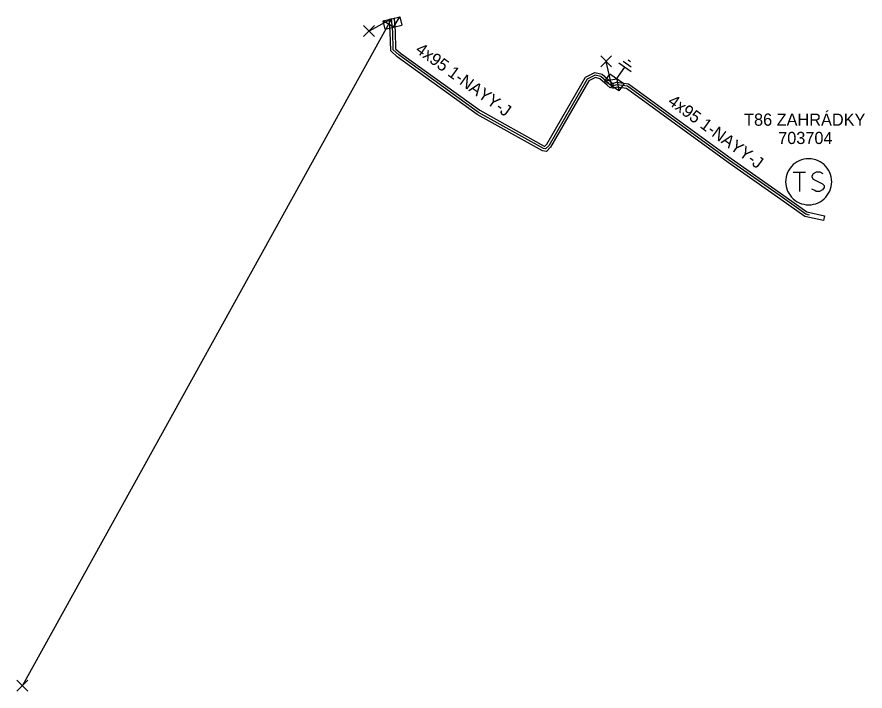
# Model space of a CAD drawing. Extents: x -540247 to -537390, y -1183890 to -1180355.
# Drawn here: x -539006.3 to -538936.7, y -1180876.4 to -1180821.1 of the extents above; entities that cross this region are included whole.
import ezdxf

# ---------------------------------------------------------------- set-up
doc = ezdxf.new("R2010")
doc.units = 0
for name, color, linetype in [('Vrstva 1', 7, 'Continuous'), ('Vrstva 14', 7, 'Continuous'), ('Vrstva 15', 7, 'Continuous'), ('Vrstva 20', 7, 'Continuous'), ('Vrstva 25', 7, 'Continuous'), ('Vrstva 26', 7, 'Continuous'), ('Vrstva 27', 7, 'Continuous'), ('Vrstva 31', 7, 'Continuous'), ('Vrstva 34', 7, 'Continuous'), ('Vrstva 5', 7, 'Continuous'), ('Vrstva 59', 7, 'Continuous'), ('Vrstva 6', 7, 'Continuous'), ('Vrstva 9', 7, 'Continuous')]:
    doc.layers.add(name, color=color, linetype=linetype)

# ---------------------------------------------------------------- blocks, each defined once
blk = doc.blocks.new('NN800')
at = {"layer": 'Vrstva 1'}
for points in [[(-0.442, 0.442), (0.442, -0.442)], [(-0.442, -0.442), (0.442, 0.442)]]:
    blk.add_lwpolyline(points, dxfattribs=at)
blk = doc.blocks.new('NN630')
at = {"layer": 'Vrstva 9'}
for points in [[(-0.003, -0.7), (-0.703, 0)], [(-0.703, -0.7), (-0.703, 0), (0.697, 0), (0.697, -0.7)], [(-0.003, -0.7), (0.697, 0)], [(-0.703, -0.7), (0.697, -0.7)]]:
    blk.add_lwpolyline(points, dxfattribs=at)
blk = doc.blocks.new('NN810')
at = {"layer": 'Vrstva 14'}
for points in [[(0.004, -0.64), (0.004, -1.89)], [(0.629, -1.89), (-0.621, -1.89)], [(0.388, -2.2), (-0.399, -2.2)], [(0.004, -2.515), (-0.124, -2.515)], [(0.137, -2.515), (0.004, -2.515)]]:
    blk.add_lwpolyline(points, dxfattribs=at)
blk = doc.blocks.new('NN610')
at = {"layer": 'Vrstva 6'}
for points in [[(1.883, -0.001), (1.872, 0.196), (1.841, 0.392), (1.79, 0.583), (1.718, 0.768), (1.629, 0.943), (1.521, 1.109), (1.397, 1.263), (1.257, 1.403), (1.103, 1.527), (0.937, 1.635), (0.761, 1.725), (0.577, 1.796), (0.19, 1.878), (0.19, 1.878), (-0.007, 1.889), (-0.205, 1.878), (-0.401, 1.847), (-0.591, 1.796), (-0.777, 1.725), (-0.952, 1.635), (-1.118, 1.527), (-1.272, 1.403), (-1.412, 1.263), (-1.536, 1.109), (-1.644, 0.943), (-1.734, 0.768), (-1.805, 0.583), (-1.856, 0.392), (-1.887, 0.196), (-1.898, -0.001), (-1.887, -0.199), (-1.856, -0.395), (-1.805, -0.585), (-1.734, -0.77), (-1.644, -0.946), (-1.536, -1.112), (-1.411, -1.266), (-1.272, -1.405), (-1.118, -1.53), (-0.952, -1.638), (-0.776, -1.728), (-0.591, -1.799), (-0.401, -1.85), (-0.205, -1.881), (-0.007, -1.892), (0.19, -1.881), (0.385, -1.85), (0.577, -1.799), (0.761, -1.728), (0.937, -1.638), (1.103, -1.53), (1.257, -1.405), (1.397, -1.266), (1.521, -1.112), (1.629, -0.946), (1.718, -0.77), (1.79, -0.585), (1.841, -0.395), (1.872, -0.199), (1.883, -0.001)], [(-1.269, 0.782), (-0.261, 0.782)], [(-0.765, 0.782), (-0.765, -0.792)], [(1.188, 0.656), (0.936, 0.782), (0.621, 0.782), (0.369, 0.656), (0.243, 0.468), (0.243, 0.404), (0.369, 0.216), (1.125, -0.162), (1.251, -0.32), (1.251, -0.478), (1.125, -0.666), (0.873, -0.792), (0.621, -0.792), (0.495, -0.73), (0.243, -0.604)]]:
    blk.add_lwpolyline(points, dxfattribs=at)

msp = doc.modelspace()

# ---------------------------------------------------------------- linework, layer by layer
at = {"layer": 'Vrstva 20'}
for points in [[(-538975.381, -1180821.253), (-538975.29, -1180822.319), (-538975.252, -1180823.72), (-538974.864, -1180824.075), (-538968.353, -1180828.771), (-538963.059, -1180831.71), (-538963.007, -1180831.721), (-538962.851, -1180831.559), (-538959.683, -1180826.058), (-538958.903, -1180825.668), (-538958.315, -1180825.818), (-538957.619, -1180826.419), (-538957.378, -1180826.629), (-538957.642, -1180826.931), (-538957.881, -1180826.721), (-538958.505, -1180826.182), (-538958.857, -1180826.092), (-538959.397, -1180826.362), (-538962.529, -1180831.801), (-538962.873, -1180832.159), (-538963.201, -1180832.089), (-538968.567, -1180829.109), (-538975.116, -1180824.385), (-538975.648, -1180823.9), (-538975.69, -1180822.341), (-538975.779, -1180821.287)], [(-538940.131, -1180837.816), (-538941.682, -1180837.487), (-538943.626, -1180836.093), (-538947.956, -1180833.053), (-538956.298, -1180826.991), (-538957.105, -1180826.873), (-538957.461, -1180826.972), (-538957.558, -1180826.588), (-538957.115, -1180826.467), (-538956.142, -1180826.609), (-538947.724, -1180832.727), (-538943.394, -1180835.767), (-538941.518, -1180837.113), (-538940.049, -1180837.424)]]:
    msp.add_lwpolyline(points, close=True, dxfattribs=at)
at = {"layer": 'Vrstva 5'}
for points in [[(-538957.51, -1180826.78), (-538957.75, -1180826.57), (-538958.41, -1180826), (-538958.88, -1180825.88), (-538959.54, -1180826.21), (-538962.69, -1180831.68), (-538962.94, -1180831.94), (-538963.13, -1180831.9), (-538968.46, -1180828.94), (-538974.99, -1180824.23), (-538975.45, -1180823.81), (-538975.49, -1180822.33), (-538975.58, -1180821.27)], [(-538941.299, -1180837.364), (-538941.6, -1180837.3), (-538943.51, -1180835.93), (-538947.84, -1180832.89), (-538956.22, -1180826.8), (-538957.11, -1180826.67), (-538957.51, -1180826.78)]]:
    msp.add_lwpolyline(points, dxfattribs=at)
at = {"layer": 'Vrstva 59'}
for points in [[(-538975.58, -1180821.27), (-539005.886, -1180875.965)], [(-538975.58, -1180821.27), (-538977.434, -1180822.267)], [(-538957.51, -1180826.78), (-538957.968, -1180824.756)]]:
    msp.add_lwpolyline(points, dxfattribs=at)

# ---------------------------------------------------------------- block references
at = {"layer": 'Vrstva 15', "rotation": 145.03775000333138}
msp.add_blockref('NN810', (-538957.51, -1180826.78), dxfattribs=at)
at = {"layer": 'Vrstva 25'}
msp.add_blockref('NN610', (-538941.347, -1180834.632), dxfattribs=at)
at = {"layer": 'Vrstva 31'}
for p, rotation in [((-538975.58, -1180821.27), 12.792587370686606), ((-538957.51, -1180826.78), 145.03443470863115)]:
    msp.add_blockref('NN630', p, dxfattribs=dict(at, rotation=rotation))
at = {"layer": 'Vrstva 34'}
for p in [(-538977.434, -1180822.267), (-538957.968, -1180824.756), (-539005.886, -1180875.965)]:
    msp.add_blockref('NN800', p, dxfattribs=at)

# ---------------------------------------------------------------- texts
at = {"layer": 'Vrstva 26'}
msp.add_text('703704', height=1, dxfattribs=at).set_placement((-538943.858, -1180831.539))
at = {"layer": 'Vrstva 27'}
msp.add_text('T86 ZAHRÁDKY', height=1, dxfattribs=at).set_placement((-538946.656, -1180830.037))
at = {"layer": 'Vrstva 6'}
for rotation, p in [(324.198, (-538973.701, -1180823.961)), (323.993, (-538952.993, -1180828.21))]:
    msp.add_text('4x95 1-NAYY-J', height=1, rotation=rotation, dxfattribs=at).set_placement(p)

doc.saveas('drawing.dxf')
